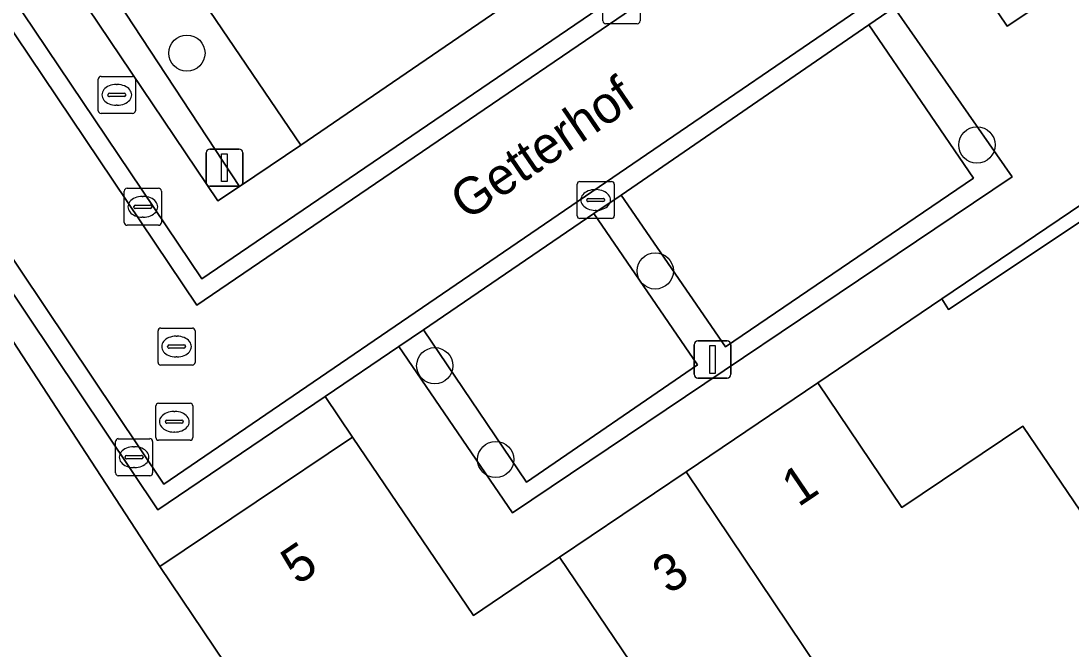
# Model space of a CAD drawing. Extents: x 158793 to 159888, y 384317 to 385256.
# Drawn here: x 158945.21 to 158973.54, y 384617.64 to 384634.6 of the extents above; entities that cross this region are included whole.
import ezdxf

# ---------------------------------------------------------------- set-up
doc = ezdxf.new("R2010")
doc.units = 0
for name, color, linetype in [('IMGEO_Boom', 7, 'Continuous'), ('IMGEO_Brandkraan', 7, 'Continuous'), ('IMGEO_Erf', 7, 'Continuous'), ('IMGEO_Groenvoorziening', 7, 'Continuous'), ('IMGEO_Haag', 7, 'Continuous'), ('IMGEO_Kolk', 7, 'Continuous'), ('IMGEO_Lichtmast', 7, 'Continuous'), ('IMGEO_Openbare_ruimte_label', 7, 'Continuous'), ('IMGEO_Pand', 7, 'Continuous'), ('IMGEO_Pand_nummerreeks', 7, 'Continuous'), ('IMGEO_Parkeervlak_open', 7, 'Continuous'), ('IMGEO_Rijbaan_lokaal_open', 7, 'Continuous'), ('IMGEO_Rioolput', 7, 'Continuous'), ('IMGEO_Voetpad_open', 7, 'Continuous')]:
    doc.layers.add(name, color=color, linetype=linetype)

msp = doc.modelspace()

# ---------------------------------------------------------------- linework, layer by layer
at = {"layer": 'IMGEO_Boom'}
for centre in [(158949.686, 384633.736), (158971.007, 384631.255), (158962.325, 384627.853), (158956.375, 384625.295), (158958.019, 384622.762)]:
    msp.add_circle(centre, 0.489, dxfattribs=at)
at = {"layer": 'IMGEO_Brandkraan'}
for p, q in [((158947.294, 384632.182), (158947.294, 384633.034)), ((158947.369, 384633.108), (158948.221, 384633.108)), ((158948.295, 384633.034), (158948.295, 384632.182)), ((158947.782, 384632.888), (158947.807, 384632.888)), ((158947.553, 384632.602), (158947.553, 384632.614)), ((158947.991, 384632.565), (158947.593, 384632.565)), ((158947.596, 384632.651), (158947.994, 384632.651)), ((158948.037, 384632.614), (158948.037, 384632.602)), ((158947.805, 384632.328), (158947.78, 384632.328)), ((158948.221, 384632.108), (158947.369, 384632.108))]:
    msp.add_line(p, q, dxfattribs=at)
for points in [[(158947.294, 384632.182), (158947.294, 384633.034)], [(158947.369, 384633.108), (158948.221, 384633.108)], [(158948.295, 384633.034), (158948.295, 384632.182)], [(158948.221, 384632.108), (158947.369, 384632.108)]]:
    msp.add_lwpolyline(points, dxfattribs=at)
for centre, radius, start, end in [((158947.371, 384633.032), 0.0765, 91.552, 178.448), ((158947.371, 384633.032), 0.0765, 91.552, 178.448), ((158948.219, 384633.032), 0.0765, 1.552, 88.448), ((158948.219, 384633.032), 0.0765, 1.552, 88.448), ((158947.593, 384632.611), 0.0403, 85.8775, 175.7526), ((158947.59, 384632.601), 0.0366, 178.938, 274.7102), ((158947.994, 384632.608), 0.043, 264.8664, 352.4533), ((158947.998, 384632.613), 0.0386, 1.7309, 96.639), ((158947.371, 384632.184), 0.0765, 181.552, 268.448), ((158947.371, 384632.184), 0.0765, 181.552, 268.448), ((158948.219, 384632.184), 0.0765, 271.552, 358.448), ((158948.219, 384632.184), 0.0765, 271.552, 358.448)]:
    msp.add_arc(centre, radius, start, end, dxfattribs=at)
for centre, major_axis, ratio, start_param, end_param in [((158947.781, 384632.608), (-0.387, 0.002), 0.722429, 4.712389, 7.853982), ((158947.806, 384632.608), (-0.39, 0.002), 0.717154, 1.570796, 4.712389)]:
    msp.add_ellipse(centre, major_axis=major_axis, ratio=ratio, start_param=start_param, end_param=end_param, dxfattribs=at)
at = {"layer": 'IMGEO_Erf'}
for points in [[(158939.596, 384653.583), (158950.919, 384636.829), (158950.958, 384636.856), (158949.554, 384638.926), (158952.648, 384641.018), (158954.049, 384638.948), (158960.703, 384643.352), (158962.287, 384644.421), (158962.382, 384644.283), (158964.327, 384645.61), (158968.134, 384639.947), (158968.418, 384639.524), (158970.35, 384636.65), (158970.621, 384636.247), (158971.818, 384634.466), (158975.716, 384637.065)], [(158945.185, 384595.438), (158953.943, 384601.409), (158954.401, 384600.762), (158954.921, 384600.028), (158955.192, 384599.646), (158962.785, 384604.676), (158963.772, 384603.26), (158967.471, 384605.617), (158966.347, 384607.28), (158964.317, 384605.908), (158963.749, 384606.758), (158962.88, 384606.177), (158960.592, 384609.598), (158961.461, 384610.179), (158960.334, 384611.865), (158958.426, 384610.581), (158956.383, 384613.618), (158955.511, 384613.032), (158955.294, 384613.355), (158953.95, 384612.451), (158948.959, 384619.868), (158942.998, 384628.997)]]:
    msp.add_lwpolyline(points, dxfattribs=at)
msp.add_lwpolyline([(158970.06, 384627.101), (158966.711, 384624.833), (158968.976, 384621.467), (158972.244, 384623.666), (158976.039, 384618.066), (158979.246, 384620.233), (158981.95, 384616.231), (158976.507, 384612.552), (158975.269, 384614.383), (158970.878, 384611.416), (158972.995, 384608.284), (158972.963, 384608.263), (158973.538, 384607.365), (158984.059, 384614.468), (158974.037, 384629.343), (158970.236, 384626.815)], close=True, dxfattribs=at)
at = {"layer": 'IMGEO_Groenvoorziening'}
for points in [[(158939.017, 384653.792), (158935.807, 384651.605), (158936.203, 384651.016), (158937.049, 384651.521), (158951.101, 384630.138), (158952.761, 384631.247), (158949.979, 384635.355), (158950.928, 384636.006)], [(158936.203, 384651.016), (158950.52, 384629.75), (158951.101, 384630.138), (158937.049, 384651.521)], [(158968.774, 384634.969), (158968.085, 384634.504), (158970.914, 384630.355), (158964.22, 384625.803), (158961.404, 384629.901), (158960.669, 384629.404), (158963.469, 384625.318), (158958.849, 384622.147), (158956.071, 384626.266), (158955.406, 384625.815), (158958.47, 384621.32), (158971.961, 384630.395)], [(158954.158, 384623.366), (158953.415, 384624.464), (158948.9, 384621.402), (158941.838, 384631.945), (158930.65, 384624.451), (158930.884, 384624.093), (158934.543, 384626.53), (158939.449, 384629.925), (158939.55, 384629.69), (158941.596, 384631.059), (158942.998, 384628.997), (158948.959, 384619.868)], [(158981.641, 384619.012), (158981.676, 384619.035), (158974.168, 384629.884), (158970.06, 384627.101), (158970.236, 384626.815), (158974.037, 384629.343), (158984.059, 384614.468), (158973.538, 384607.365), (158972.963, 384608.263), (158972.484, 384607.938), (158973.336, 384606.67), (158984.689, 384614.403), (158984.677, 384614.451)]]:
    msp.add_lwpolyline(points, close=True, dxfattribs=at)
at = {"layer": 'IMGEO_Haag'}
for points in [[(158936.203, 384651.016), (158950.52, 384629.75), (158951.101, 384630.138), (158937.049, 384651.521)], [(158954.158, 384623.366), (158953.415, 384624.464), (158948.9, 384621.402), (158941.838, 384631.945), (158930.65, 384624.451), (158930.884, 384624.093), (158934.543, 384626.53), (158939.449, 384629.925), (158939.55, 384629.69), (158941.596, 384631.059), (158942.998, 384628.997), (158948.959, 384619.868)], [(158974.168, 384629.884), (158970.06, 384627.101), (158970.236, 384626.815), (158974.037, 384629.343), (158984.059, 384614.468), (158973.538, 384607.365), (158972.963, 384608.263), (158972.484, 384607.938), (158973.336, 384606.67), (158984.689, 384614.403), (158984.677, 384614.451), (158981.641, 384619.012), (158981.676, 384619.035)]]:
    msp.add_lwpolyline(points, close=True, dxfattribs=at)
at = {"layer": 'IMGEO_Kolk'}
for p, q in [((158960.914, 384634.604), (158960.914, 384635.456)), ((158961.915, 384635.456), (158961.915, 384634.604)), ((158961.841, 384634.53), (158960.989, 384634.53)), ((158960.217, 384629.344), (158960.217, 384630.196)), ((158960.292, 384630.27), (158961.144, 384630.27)), ((158961.218, 384630.196), (158961.218, 384629.344)), ((158947.995, 384629.16), (158947.995, 384630.012)), ((158948.07, 384630.086), (158948.922, 384630.086)), ((158948.996, 384630.012), (158948.996, 384629.16)), ((158960.705, 384630.05), (158960.73, 384630.05)), ((158948.297, 384629.629), (158948.695, 384629.629)), ((158948.483, 384629.866), (158948.508, 384629.866)), ((158960.476, 384629.764), (158960.476, 384629.776)), ((158960.914, 384629.727), (158960.516, 384629.727)), ((158960.519, 384629.813), (158960.917, 384629.813)), ((158960.96, 384629.776), (158960.96, 384629.764)), ((158948.254, 384629.58), (158948.254, 384629.592)), ((158948.692, 384629.543), (158948.294, 384629.543)), ((158948.738, 384629.592), (158948.738, 384629.58)), ((158960.728, 384629.49), (158960.703, 384629.49)), ((158948.922, 384629.086), (158948.07, 384629.086)), ((158948.506, 384629.306), (158948.481, 384629.306)), ((158961.144, 384629.27), (158960.292, 384629.27)), ((158947.76, 384622.398), (158947.76, 384623.25)), ((158947.835, 384623.324), (158948.687, 384623.324)), ((158948.248, 384623.104), (158948.273, 384623.104)), ((158948.761, 384623.25), (158948.761, 384622.398)), ((158948.019, 384622.818), (158948.019, 384622.83)), ((158948.062, 384622.867), (158948.46, 384622.867)), ((158948.503, 384622.83), (158948.503, 384622.818)), ((158948.457, 384622.781), (158948.059, 384622.781)), ((158948.271, 384622.544), (158948.246, 384622.544)), ((158948.687, 384622.324), (158947.835, 384622.324))]:
    msp.add_line(p, q, dxfattribs=at)
for points in [[(158960.914, 384634.604), (158960.914, 384635.456)], [(158961.915, 384635.456), (158961.915, 384634.604)], [(158961.841, 384634.53), (158960.989, 384634.53)], [(158960.217, 384629.344), (158960.217, 384630.196)], [(158960.292, 384630.27), (158961.144, 384630.27)], [(158961.218, 384630.196), (158961.218, 384629.344)], [(158947.995, 384629.16), (158947.995, 384630.012)], [(158948.07, 384630.086), (158948.922, 384630.086)], [(158948.996, 384630.012), (158948.996, 384629.16)], [(158948.922, 384629.086), (158948.07, 384629.086)], [(158961.144, 384629.27), (158960.292, 384629.27)], [(158947.76, 384622.398), (158947.76, 384623.25)], [(158947.835, 384623.324), (158948.687, 384623.324)], [(158948.761, 384623.25), (158948.761, 384622.398)], [(158948.687, 384622.324), (158947.835, 384622.324)]]:
    msp.add_lwpolyline(points, dxfattribs=at)
for centre, radius, start, end in [((158960.991, 384634.606), 0.0765, 181.552, 268.448), ((158960.991, 384634.606), 0.0765, 181.552, 268.448), ((158961.839, 384634.606), 0.0765, 271.552, 358.448), ((158961.839, 384634.606), 0.0765, 271.552, 358.448), ((158960.294, 384630.194), 0.0765, 91.552, 178.448), ((158960.294, 384630.194), 0.0765, 91.552, 178.448), ((158961.142, 384630.194), 0.0765, 1.552, 88.448), ((158961.142, 384630.194), 0.0765, 1.552, 88.448), ((158948.072, 384630.01), 0.0765, 91.552, 178.448), ((158948.072, 384630.01), 0.0765, 91.552, 178.448), ((158948.92, 384630.01), 0.0765, 1.552, 88.448), ((158948.92, 384630.01), 0.0765, 1.552, 88.448), ((158948.294, 384629.589), 0.0403, 85.8775, 175.7526), ((158948.699, 384629.591), 0.0386, 1.7309, 96.639), ((158960.516, 384629.773), 0.0403, 85.8775, 175.7526), ((158960.513, 384629.763), 0.0366, 178.938, 274.7102), ((158960.917, 384629.77), 0.043, 264.8664, 352.4533), ((158960.921, 384629.775), 0.0386, 1.7309, 96.639), ((158948.291, 384629.579), 0.0366, 178.938, 274.7102), ((158948.695, 384629.586), 0.043, 264.8664, 352.4533), ((158960.294, 384629.346), 0.0765, 181.552, 268.448), ((158960.294, 384629.346), 0.0765, 181.552, 268.448), ((158961.142, 384629.346), 0.0765, 271.552, 358.448), ((158961.142, 384629.346), 0.0765, 271.552, 358.448), ((158948.072, 384629.162), 0.0765, 181.552, 268.448), ((158948.072, 384629.162), 0.0765, 181.552, 268.448), ((158948.92, 384629.162), 0.0765, 271.552, 358.448), ((158948.92, 384629.162), 0.0765, 271.552, 358.448), ((158947.837, 384623.248), 0.0765, 91.552, 178.448), ((158947.837, 384623.248), 0.0765, 91.552, 178.448), ((158948.685, 384623.248), 0.0765, 1.552, 88.448), ((158948.685, 384623.248), 0.0765, 1.552, 88.448), ((158948.059, 384622.827), 0.0403, 85.8775, 175.7526), ((158948.056, 384622.817), 0.0366, 178.938, 274.7102), ((158948.46, 384622.824), 0.043, 264.8664, 352.4533), ((158948.464, 384622.829), 0.0386, 1.7309, 96.639), ((158947.837, 384622.4), 0.0765, 181.552, 268.448), ((158947.837, 384622.4), 0.0765, 181.552, 268.448), ((158948.685, 384622.4), 0.0765, 271.552, 358.448), ((158948.685, 384622.4), 0.0765, 271.552, 358.448)]:
    msp.add_arc(centre, radius, start, end, dxfattribs=at)
for centre, major_axis, ratio, start_param, end_param in [((158960.704, 384629.77), (-0.387, 0.002), 0.722429, 4.712389, 7.853982), ((158960.729, 384629.77), (-0.39, 0.002), 0.717154, 1.570796, 4.712389), ((158948.482, 384629.586), (-0.387, 0.002), 0.722429, 4.712389, 7.853982), ((158948.507, 384629.586), (-0.39, 0.002), 0.717154, 1.570796, 4.712389), ((158948.247, 384622.824), (-0.387, 0.002), 0.722429, 4.712389, 7.853982), ((158948.272, 384622.824), (-0.39, 0.002), 0.717154, 1.570796, 4.712389)]:
    msp.add_ellipse(centre, major_axis=major_axis, ratio=ratio, start_param=start_param, end_param=end_param, dxfattribs=at)
at = {"layer": 'IMGEO_Lichtmast'}
for p, q in [((158950.204, 384630.245), (158950.204, 384631.045)), ((158950.204, 384631.045), (158950.204, 384630.245)), ((158950.304, 384631.145), (158951.094, 384631.145)), ((158951.094, 384631.145), (158950.304, 384631.145)), ((158951.194, 384631.045), (158951.194, 384630.245)), ((158951.194, 384630.245), (158951.194, 384631.045)), ((158951.094, 384630.145), (158950.304, 384630.145)), ((158950.304, 384630.145), (158951.094, 384630.145)), ((158963.474, 384625.962), (158964.264, 384625.962)), ((158964.264, 384625.962), (158963.474, 384625.962)), ((158963.374, 384625.062), (158963.374, 384625.862)), ((158963.374, 384625.862), (158963.374, 384625.062)), ((158964.364, 384625.862), (158964.364, 384625.062)), ((158964.364, 384625.062), (158964.364, 384625.862)), ((158964.264, 384624.962), (158963.474, 384624.962)), ((158963.474, 384624.962), (158964.264, 384624.962))]:
    msp.add_line(p, q, dxfattribs=at)
for points in [[(158950.624, 384631.02), (158950.774, 384631.02), (158950.774, 384630.27), (158950.624, 384630.27), (158950.624, 384631.02)], [(158963.794, 384625.837), (158963.944, 384625.837), (158963.944, 384625.087), (158963.794, 384625.087), (158963.794, 384625.837)]]:
    msp.add_lwpolyline(points, dxfattribs=at)
for centre, start, end in [((158950.304, 384631.045), 90, 180), ((158950.304, 384631.045), 90, 180), ((158951.094, 384631.045), 0, 90), ((158951.094, 384631.045), 360, 90), ((158950.304, 384630.245), 180, 270), ((158950.304, 384630.245), 180, 270), ((158951.094, 384630.245), 270, 0), ((158951.094, 384630.245), 270, 0), ((158963.474, 384625.862), 90, 180), ((158963.474, 384625.862), 90, 180), ((158964.264, 384625.862), 0, 90), ((158964.264, 384625.862), 360, 90), ((158963.474, 384625.062), 180, 270), ((158963.474, 384625.062), 180, 270), ((158964.264, 384625.062), 270, 0), ((158964.264, 384625.062), 270, 0)]:
    msp.add_arc(centre, 0.1, start, end, dxfattribs=at)
at = {"layer": 'IMGEO_Pand'}
for points in [[(158968.976, 384621.467), (158966.711, 384624.833), (158963.155, 384622.43), (158970.65, 384611.266), (158970.878, 384611.416), (158975.269, 384614.383), (158976.507, 384612.552), (158981.95, 384616.231), (158979.246, 384620.233), (158976.039, 384618.066), (158972.244, 384623.666)], [(158959.741, 384620.123), (158957.417, 384618.552), (158954.158, 384623.366), (158948.959, 384619.868), (158953.95, 384612.451), (158955.294, 384613.355), (158955.511, 384613.032), (158956.383, 384613.618), (158958.426, 384610.581), (158960.334, 384611.865), (158963.758, 384614.178)], [(158963.155, 384622.43), (158959.741, 384620.123), (158963.758, 384614.178), (158960.334, 384611.865), (158961.461, 384610.179), (158960.592, 384609.598), (158962.88, 384606.177), (158963.749, 384606.758), (158964.317, 384605.908), (158966.347, 384607.28), (158967.471, 384605.617), (158967.706, 384605.269), (158967.965, 384604.885), (158972.484, 384607.938), (158972.963, 384608.263), (158972.995, 384608.284), (158970.878, 384611.416), (158970.65, 384611.266)]]:
    msp.add_lwpolyline(points, close=True, dxfattribs=at)
at = {"layer": 'IMGEO_Parkeervlak_open'}
for points in [[(158959.328, 384635.75), (158956.541, 384639.854), (158951.302, 384636.262), (158950.928, 384636.006), (158949.979, 384635.355), (158952.761, 384631.247)], [(158968.085, 384634.504), (158961.404, 384629.901), (158964.22, 384625.803), (158970.914, 384630.355)], [(158960.669, 384629.404), (158956.071, 384626.266), (158958.849, 384622.147), (158963.469, 384625.318)]]:
    msp.add_lwpolyline(points, close=True, dxfattribs=at)
at = {"layer": 'IMGEO_Rijbaan_lokaal_open'}
for points in [[(158920.881, 384670.173), (158923.955, 384665.633), (158949.957, 384626.932), (158968.418, 384639.524), (158968.134, 384639.947), (158950.085, 384627.638), (158924.353, 384665.905), (158921.285, 384670.455)], [(158941.972, 384632.67), (158949.064, 384622.099), (158970.35, 384636.65), (158968.418, 384639.524), (158949.957, 384626.932), (158923.955, 384665.633), (158920.881, 384670.173)]]:
    msp.add_lwpolyline(points, dxfattribs=at)
msp.add_lwpolyline([(158941.972, 384632.67), (158918.871, 384617.212), (158919.186, 384616.765), (158928.046, 384622.707), (158929.151, 384623.447), (158930.65, 384624.451), (158941.838, 384631.945), (158948.9, 384621.402), (158953.415, 384624.464), (158955.406, 384625.815), (158956.071, 384626.266), (158960.669, 384629.404), (158961.404, 384629.901), (158968.085, 384634.504), (158968.774, 384634.969), (158970.621, 384636.247), (158970.35, 384636.65), (158949.064, 384622.099)], close=True, dxfattribs=at)
at = {"layer": 'IMGEO_Rioolput'}
for p, q in [((158948.906, 384625.385), (158948.906, 384626.237)), ((158948.981, 384626.311), (158949.833, 384626.311)), ((158949.907, 384626.237), (158949.907, 384625.385)), ((158949.394, 384626.091), (158949.419, 384626.091)), ((158949.165, 384625.805), (158949.165, 384625.817)), ((158949.603, 384625.768), (158949.205, 384625.768)), ((158949.208, 384625.854), (158949.606, 384625.854)), ((158949.649, 384625.817), (158949.649, 384625.805)), ((158949.417, 384625.531), (158949.392, 384625.531)), ((158949.833, 384625.311), (158948.981, 384625.311)), ((158948.921, 384624.282), (158949.773, 384624.282)), ((158948.846, 384623.356), (158948.846, 384624.208)), ((158949.334, 384624.062), (158949.359, 384624.062)), ((158949.847, 384624.208), (158949.847, 384623.356)), ((158949.105, 384623.776), (158949.105, 384623.788)), ((158949.543, 384623.739), (158949.145, 384623.739)), ((158949.148, 384623.825), (158949.546, 384623.825)), ((158949.589, 384623.788), (158949.589, 384623.776)), ((158949.357, 384623.502), (158949.332, 384623.502)), ((158949.773, 384623.282), (158948.921, 384623.282))]:
    msp.add_line(p, q, dxfattribs=at)
for points in [[(158948.906, 384625.385), (158948.906, 384626.237)], [(158948.981, 384626.311), (158949.833, 384626.311)], [(158949.907, 384626.237), (158949.907, 384625.385)], [(158949.833, 384625.311), (158948.981, 384625.311)], [(158948.921, 384624.282), (158949.773, 384624.282)], [(158948.846, 384623.356), (158948.846, 384624.208)], [(158949.847, 384624.208), (158949.847, 384623.356)], [(158949.773, 384623.282), (158948.921, 384623.282)]]:
    msp.add_lwpolyline(points, dxfattribs=at)
for centre, radius, start, end in [((158948.983, 384626.235), 0.0765, 91.552, 178.448), ((158948.983, 384626.235), 0.0765, 91.552, 178.448), ((158949.831, 384626.235), 0.0765, 1.552, 88.448), ((158949.831, 384626.235), 0.0765, 1.552, 88.448), ((158949.205, 384625.814), 0.0403, 85.8775, 175.7526), ((158949.202, 384625.804), 0.0366, 178.938, 274.7102), ((158949.606, 384625.811), 0.043, 264.8664, 352.4533), ((158949.61, 384625.816), 0.0386, 1.7309, 96.639), ((158948.983, 384625.387), 0.0765, 181.552, 268.448), ((158948.983, 384625.387), 0.0765, 181.552, 268.448), ((158949.831, 384625.387), 0.0765, 271.552, 358.448), ((158949.831, 384625.387), 0.0765, 271.552, 358.448), ((158948.923, 384624.206), 0.0765, 91.552, 178.448), ((158948.923, 384624.206), 0.0765, 91.552, 178.448), ((158949.771, 384624.206), 0.0765, 1.552, 88.448), ((158949.771, 384624.206), 0.0765, 1.552, 88.448), ((158949.145, 384623.785), 0.0403, 85.8775, 175.7526), ((158949.142, 384623.775), 0.0366, 178.938, 274.7102), ((158949.546, 384623.782), 0.043, 264.8664, 352.4533), ((158949.55, 384623.787), 0.0386, 1.7309, 96.639), ((158948.923, 384623.358), 0.0765, 181.552, 268.448), ((158948.923, 384623.358), 0.0765, 181.552, 268.448), ((158949.771, 384623.358), 0.0765, 271.552, 358.448), ((158949.771, 384623.358), 0.0765, 271.552, 358.448)]:
    msp.add_arc(centre, radius, start, end, dxfattribs=at)
for centre, major_axis, ratio, start_param, end_param in [((158949.393, 384625.811), (-0.387, 0.002), 0.722429, 4.712389, 7.853982), ((158949.418, 384625.811), (-0.39, 0.002), 0.717154, 1.570796, 4.712389), ((158949.333, 384623.782), (-0.387, 0.002), 0.722429, 4.712389, 7.853982), ((158949.358, 384623.782), (-0.39, 0.002), 0.717154, 1.570796, 4.712389)]:
    msp.add_ellipse(centre, major_axis=major_axis, ratio=ratio, start_param=start_param, end_param=end_param, dxfattribs=at)
at = {"layer": 'IMGEO_Voetpad_open'}
for points in [[(158921.285, 384670.455), (158924.353, 384665.905), (158950.085, 384627.638), (158968.134, 384639.947), (158964.327, 384645.61), (158962.382, 384644.283), (158965.367, 384639.89), (158964.741, 384639.472), (158960.089, 384636.266), (158959.328, 384635.75), (158952.761, 384631.247), (158951.101, 384630.138), (158950.52, 384629.75), (158936.203, 384651.016), (158935.807, 384651.605), (158931.31, 384658.301), (158930.791, 384659.038), (158926.191, 384665.854), (158925.456, 384666.95), (158924.962, 384667.694), (158922.109, 384671.989)], [(158975.716, 384637.065), (158971.818, 384634.466), (158970.621, 384636.247), (158968.774, 384634.969), (158971.961, 384630.395), (158958.47, 384621.32), (158955.406, 384625.815), (158953.415, 384624.464), (158954.158, 384623.366), (158957.417, 384618.552), (158959.741, 384620.123), (158963.155, 384622.43), (158966.711, 384624.833), (158970.06, 384627.101), (158974.168, 384629.884)]]:
    msp.add_lwpolyline(points, dxfattribs=at)

# ---------------------------------------------------------------- texts
at = {"layer": 'IMGEO_Openbare_ruimte_label'}
msp.add_text('Getterhof', height=1, rotation=34.3256, dxfattribs=at).set_placement((158957.246, 384629.194))
at = {"layer": 'IMGEO_Pand_nummerreeks'}
for s, rotation, p in [('1', 34.0501, (158966.187, 384621.462)), ('5', 33.9322, (158952.67, 384619.352)), ('3', 34.0509, (158962.693, 384619.1))]:
    msp.add_text(s, height=1, rotation=rotation, dxfattribs=at).set_placement(p)

doc.saveas('drawing.dxf')
